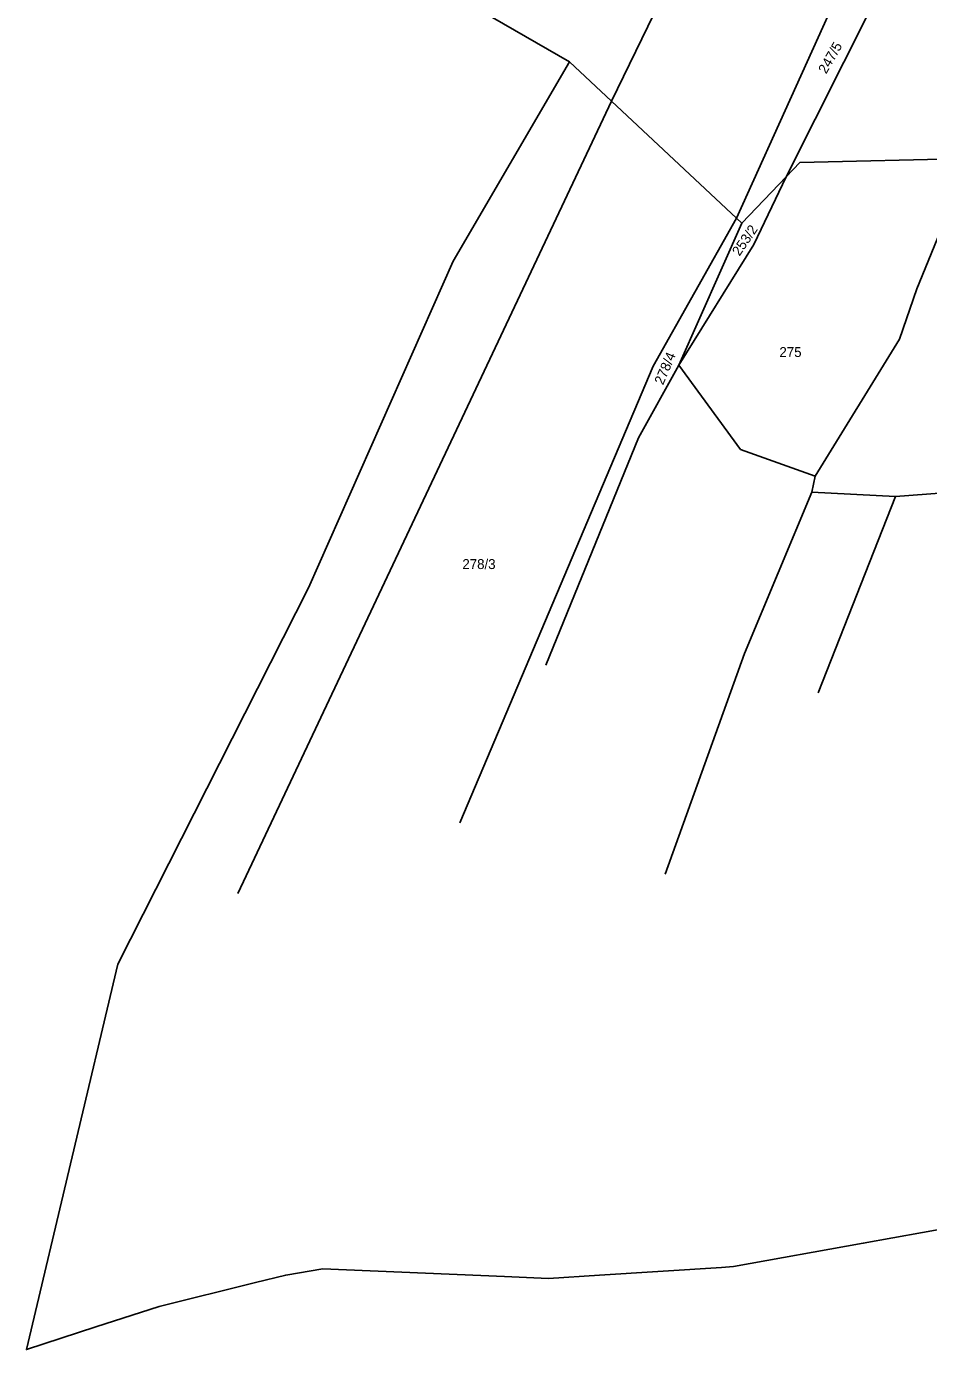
# Model space of a CAD drawing. Extents: x -743888 to -742027, y -1128394 to -1126768.
# Drawn here: x -743416.2 to -743261.6, y -1128308.3 to -1128081.8 of the extents above; entities that cross this region are included whole.
import ezdxf

# ---------------------------------------------------------------- set-up
doc = ezdxf.new("R2010")
doc.units = 0
for name, color, linetype in [('Vrstva 1', 7, 'Continuous'), ('Vrstva 13', 7, 'Continuous'), ('Vrstva 18', 7, 'Continuous'), ('Vrstva 52', 7, 'Continuous'), ('Vrstva 6', 7, 'Continuous')]:
    doc.layers.add(name, color=color, linetype=linetype)

msp = doc.modelspace()

# ---------------------------------------------------------------- linework, layer by layer
at = {"layer": 'Vrstva 1'}
for points in [[(-743323.15, -1128087.88), (-743315.96, -1128094.6)], [(-743315.96, -1128094.6), (-743294.54, -1128114.63)], [(-743283.67, -1128105.07), (-743254.5, -1128104.39)], [(-743286.03, -1128107.53), (-743283.67, -1128105.07)], [(-743293.63, -1128115.48), (-743286.03, -1128107.53)], [(-743304.44, -1128139.77), (-743293.63, -1128115.48)], [(-743294.54, -1128114.63), (-743293.63, -1128115.48)]]:
    msp.add_lwpolyline(points, dxfattribs=at)
at = {"layer": 'Vrstva 13'}
for points in [[(-743338.22, -1128079.2), (-743323.15, -1128087.88)], [(-743343.09, -1128121.96), (-743323.15, -1128087.88)], [(-743367.87, -1128177.92), (-743343.09, -1128121.96)], [(-743400.49, -1128242.34), (-743367.87, -1128177.92)]]:
    msp.add_lwpolyline(points, dxfattribs=at)
at = {"layer": 'Vrstva 52'}
msp.add_lwpolyline([(-743338.22, -1128079.2), (-743323.15, -1128087.88), (-743343.09, -1128121.96), (-743367.87, -1128177.92), (-743400.49, -1128242.34), (-743416.17, -1128308.32), (-743404.29, -1128304.45), (-743393.46, -1128300.93), (-743376.91, -1128296.84), (-743371.74, -1128295.57), (-743365.4, -1128294.5), (-743334.3, -1128295.83), (-743326.74, -1128296.15), (-743317.99, -1128295.59), (-743297.09, -1128294.26), (-743295.06, -1128294.13), (-743272.83, -1128290.13), (-743247.43, -1128285.55)], dxfattribs=at)
at = {"layer": 'Vrstva 6'}
for points in [[(-743286.03, -1128107.53), (-743261.3, -1128058.36)], [(-743315.96, -1128094.6), (-743300.41, -1128062.62)], [(-743294.54, -1128114.63), (-743274.12, -1128069.36)], [(-743379.94, -1128230.27), (-743315.96, -1128094.6)], [(-743263.65, -1128126.74), (-743254.5, -1128104.39)], [(-743291.6, -1128119.11), (-743286.03, -1128107.53)], [(-743308.81, -1128139.96), (-743294.54, -1128114.63)], [(-743304.44, -1128139.77), (-743291.6, -1128119.11)], [(-743266.64, -1128135.34), (-743263.65, -1128126.74)], [(-743281.08, -1128158.78), (-743266.64, -1128135.34)], [(-743341.96, -1128218.17), (-743308.81, -1128139.96)], [(-743304.44, -1128139.77), (-743311.35, -1128152.21), (-743327.18, -1128191.16)], [(-743304.44, -1128139.77), (-743293.84, -1128154.22)], [(-743293.84, -1128154.22), (-743281.08, -1128158.78)], [(-743281.61, -1128161.52), (-743281.08, -1128158.78)], [(-743267.29, -1128162.3), (-743246.85, -1128160.74)], [(-743293.18, -1128189.13), (-743281.61, -1128161.52)], [(-743281.61, -1128161.52), (-743267.29, -1128162.3)], [(-743280.53, -1128195.87), (-743267.29, -1128162.3)], [(-743306.77, -1128226.91), (-743293.18, -1128189.13)]]:
    msp.add_lwpolyline(points, dxfattribs=at)

# ---------------------------------------------------------------- texts
at = {"layer": 'Vrstva 18'}
for s, rotation, p in [('247/5', 60.1569, (-743279.18, -1128090.03)), ('253/2', 55.6393, (-743294.03, -1128121.22)), ('278/4', 67.0438, (-743307.12, -1128143.28))]:
    msp.add_text(s, height=1.7, rotation=rotation, dxfattribs=at).set_placement(p)
for s, p in [('275', (-743287.19, -1128138.4)), ('278/3', (-743341.5, -1128174.7))]:
    msp.add_text(s, height=1.7, dxfattribs=at).set_placement(p)

doc.saveas('drawing.dxf')
